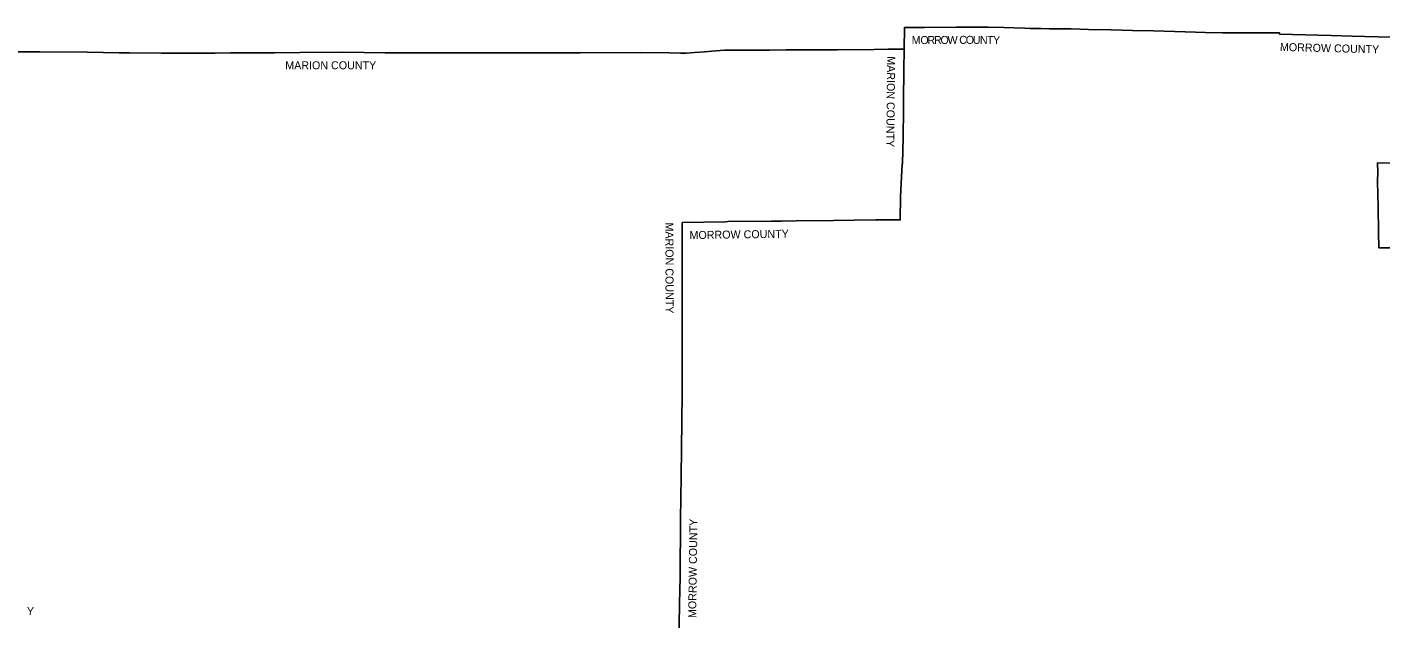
# Model space of a CAD drawing. Extents: x 1674899 to 2057726, y 653888 to 988278.
# Drawn here: x 1759512 to 1928708, y 914248 to 988278 of the extents above; entities that cross this region are included whole.
import ezdxf

# ---------------------------------------------------------------- set-up
doc = ezdxf.new("R2010")
doc.units = 0
doc.layers.add('GM_X_Adjacent_County', color=7, linetype='Continuous')
doc.layers.add('GM_X_Adjacent_County_Text', color=7, linetype='Continuous')

msp = doc.modelspace()

# ---------------------------------------------------------------- linework, layer by layer
at = {"layer": 'GM_X_Adjacent_County'}
for points in [[(1840970, 910855), (1841058, 916141), (1841113, 919520), (1841192, 926713), (1841249, 932050), (1841362, 942439), (1841377, 947941), (1841392, 953202), (1841402, 956488), (1841397, 958575), (1841394, 960342), (1841392, 961182), (1841387, 963824), (1846780, 963929), (1847071, 963938), (1852487, 963992), (1853408, 964004), (1853786, 964009), (1855618, 964050), (1860298, 964101), (1862894, 964131), (1865546, 964151), (1868643, 964155), (1868654, 967077), (1868896, 971111), (1868903, 971230), (1868993, 974454), (1868995, 974673), (1869028, 977767), (1869041, 979034), (1869083, 982941), (1869110, 985528), (1869183, 988230), (1871661, 988243), (1875677, 988261), (1877300, 988258), (1877944, 988247), (1878309, 988257), (1879625, 988278), (1881591, 988207), (1884186, 988121), (1884889, 988110), (1886245, 988079), (1886959, 988065), (1887247, 988078), (1887277, 988068), (1887305, 988061), (1887332, 988057), (1887406, 988055), (1887534, 988056), (1887954, 988052), (1888291, 988047), (1888567, 988043), (1888789, 988041), (1889241, 988035), (1890006, 988038), (1892176, 987990), (1895013, 987926), (1897647, 987858), (1900287, 987794), (1904231, 987686), (1905517, 987636), (1906801, 987606), (1908915, 987558), (1916031, 987559), (1916031, 987390), (1922491, 987223), (1925127, 987155), (1933106, 986948)], [(1756190, 985192), (1761103, 985171), (1767041, 985145), (1771012, 985062), (1771919, 985044), (1772302, 985037), (1776297, 985001), (1777600, 984996), (1783032, 985019), (1784945, 985035), (1785146, 985038), (1785879, 985049), (1788294, 985063), (1790446, 985072), (1793655, 985091), (1798944, 985119), (1804246, 985060), (1804440, 985061), (1804717, 985058), (1805634, 985060), (1809554, 985051), (1810918, 985033), (1820580, 985048), (1828627, 985061), (1836217, 985098), (1839819, 985043), (1841171, 985014), (1841533, 985009), (1841872, 985027), (1842914, 985093), (1844196, 985194), (1845074, 985259), (1845572, 985289), (1846658, 985379), (1846800, 985384), (1849534, 985395), (1852293, 985374), (1854335, 985412), (1854489, 985417), (1854939, 985417), (1859023, 985435), (1860805, 985437), (1865333, 985487), (1867146, 985506), (1869110, 985528), (1869083, 982941), (1869041, 979034), (1869028, 977767), (1868995, 974673), (1868993, 974454), (1868903, 971230), (1868896, 971111), (1868654, 967077), (1868643, 964155), (1865546, 964151), (1862894, 964131), (1860298, 964101), (1855618, 964050), (1853786, 964009), (1853408, 964004), (1852487, 963992), (1847071, 963938), (1846780, 963929), (1841387, 963824), (1841392, 961182), (1841394, 960342), (1841397, 958575), (1841402, 956488), (1841392, 953202), (1841377, 947941), (1841362, 942439), (1841249, 932050), (1841192, 926713), (1841113, 919520), (1841058, 916141), (1840970, 910855)], [(1929986, 971246), (1928265, 971283), (1928303, 970087), (1928288, 969028), (1928289, 968947), (1928357, 965797), (1928425, 962614), (1928467, 960653), (1930020, 960674)]]:
    msp.add_lwpolyline(points, dxfattribs=at)

# ---------------------------------------------------------------- texts
at = {"layer": 'GM_X_Adjacent_County_Text'}
for s, rotation, p in [('M', 0.23361, (1870067, 986147)), ('O', 0.23404, (1871154, 986151)), ('R', 0.23393, (1872038, 986155)), ('R', 0.23486, (1872852, 986158)), ('O', 0.2327, (1873666, 986161)), ('W', 0.23455, (1874551, 986165)), ('C', 0.2292, (1876007, 986171)), ('O', 0.19791, (1876821, 986174)), ('U', 0.0435, (1877705, 986177)), ('N', 359.63898, (1878587, 986178)), ('T', 359.14628, (1879469, 986172)), ('Y', 358.25336, (1880213, 986161)), ('MORROW COUNTY', 358.53833, (1916077, 985298)), ('MARION COUNTY', 0.00037, (1791781, 982996)), ('MARION COUNTY', 269.36981, (1867009, 984630)), ('MARION COUNTY', 270.02428, (1839297, 963828)), ('MORROW COUNTY', 0.82044, (1842307, 961753)), ('MORROW COUNTY', 89.24604, (1843131, 914360)), ('Y', 358.42091, (1759466, 914747))]:
    msp.add_text(s, height=1000, rotation=rotation, dxfattribs=at).set_placement(p)

doc.saveas('drawing.dxf')
